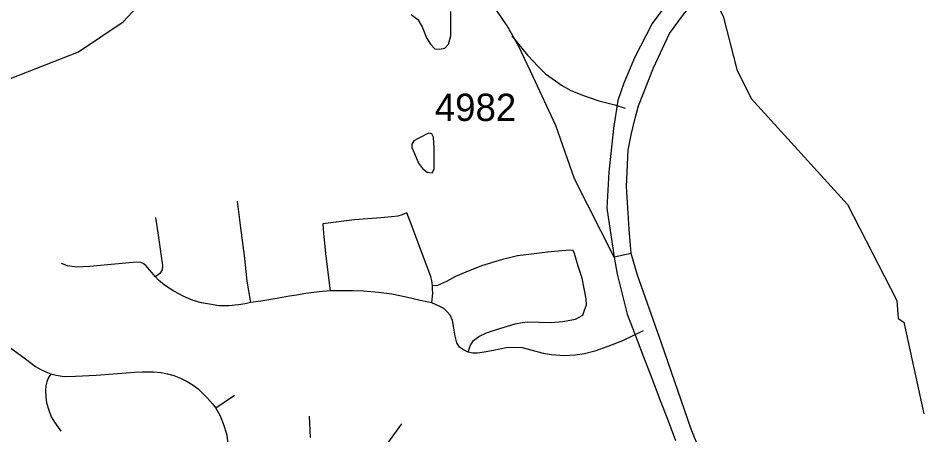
# Model space of a CAD drawing. Extents: x 1383679 to 1536984, y 460658 to 651027.
# Drawn here: x 1442977 to 1447116, y 469651 to 471554 of the extents above; entities that cross this region are included whole.
import ezdxf

# ---------------------------------------------------------------- set-up
doc = ezdxf.new("R2010")
doc.units = 0
for name, color, linetype in [('Exist Hydrographic Creek Single Shore', 7, 'Continuous'), ('Exist Hydrographic Misc Water Feature', 7, 'Continuous'), ('Exist Road Non-System Type 51', 7, 'Continuous'), ('Exist Road Primary US Divided Attributed', 7, 'Continuous'), ('Exist Road Secondary Type 51 Attributed', 7, 'Continuous'), ('Exist Road Secondary Type 51 Number Label', 7, 'Continuous')]:
    doc.layers.add(name, color=color, linetype=linetype)

msp = doc.modelspace()

# ---------------------------------------------------------------- linework, layer by layer
at = {"layer": 'Exist Hydrographic Creek Single Shore'}
msp.add_lwpolyline([(1442699, 471184.5), (1443253.1, 471399.8), (1443456.1, 471536.8), (1443770, 471875.2), (1444283.1, 472075), (1444619, 472242.1), (1444791.1, 472547.2), (1445263.1, 472321.1), (1445451, 472153.2), (1445649.1, 472024.5), (1445764.1, 471913.9), (1446012.1, 471807.1), (1446143.1, 471673.2), (1446199.1, 471563.7), (1446261.1, 471319.6), (1446326.1, 471187), (1446767.1, 470702.1), (1446992.1, 470264.3), (1446999.1, 470182.2), (1447024.1, 470165.2), (1447116.1, 469746.5)], dxfattribs=at)
at = {"layer": 'Exist Hydrographic Misc Water Feature'}
for points in [[(1444773.4, 471570.1), (1444803, 471547.4), (1444822.5, 471515), (1444843.5, 471464.5), (1444861, 471434.6), (1444880.6, 471413.7), (1444902.6, 471411.6), (1444926.7, 471416.8), (1444943, 471434.6), (1444953.7, 471472.9), (1444954.9, 471534.4), (1444953.7, 471584.5)], [(1444811.1, 471007.3), (1444784.9, 470993.8), (1444776.6, 470977.6), (1444776.4, 470963.6), (1444787.9, 470935.5), (1444807, 470890.8), (1444824.6, 470866.6), (1444846.3, 470850.6), (1444868.2, 470847.7), (1444878.6, 470863.9), (1444878.3, 470959.9), (1444875.2, 471010), (1444867.5, 471025.8), (1444851.5, 471028.6), (1444811.1, 471007.3)]]:
    msp.add_lwpolyline(points, dxfattribs=at)
at = {"layer": 'Exist Road Non-System Type 51'}
for p, q in [((1444306.9, 469735.9), (1444312.1, 469639.1)), ((1444729.4, 469701.7), (1444664.4, 469613.3))]:
    msp.add_line(p, q, dxfattribs=at)
for points in [[(1445233, 471473.6), (1445305.2, 471385.4), (1445353.9, 471333.4), (1445386.6, 471300.2), (1445431.8, 471266.9), (1445460, 471247.1), (1445500.1, 471225.2), (1445556.6, 471201.5), (1445631, 471175.7), (1445703, 471157.3), (1445750.9, 471143.5)], [(1443977.9, 470717.7), (1443993.1, 470595.6), (1444009.1, 470469.8), (1444022.1, 470352.2), (1444038.1, 470254.8)], [(1444870.9, 470331.1), (1444868, 470355.8), (1444862.2, 470373.9), (1444820.9, 470485.8), (1444778.6, 470597), (1444753.2, 470665.3), (1444731.4, 470655.2), (1444712.5, 470650.1), (1444683.4, 470645.8), (1444634.8, 470641.3), (1444513.4, 470632.7), (1444369.5, 470615.2), (1444371.6, 470571.6), (1444381.9, 470479.3), (1444393.5, 470379.8), (1444402.9, 470308.5)], [(1443604.6, 470643.8), (1443615.5, 470572.8), (1443627.5, 470487.6), (1443636.2, 470424.3), (1443635.1, 470403.6), (1443624.2, 470388.2), (1443605, 470372.5)], [(1445033, 470028), (1445043.1, 470057.1), (1445057.8, 470081.8), (1445081.6, 470099.2), (1445117.4, 470116.7), (1445163.1, 470131.2), (1445248.9, 470158.1), (1445280.1, 470163.9), (1445306.2, 470166.1), (1445412.4, 470163.9), (1445466.1, 470169), (1445524.2, 470178.4), (1445556.9, 470197.3), (1445565.5, 470220.7), (1445573.6, 470245.1), (1445572, 470271.2), (1445563.9, 470318.7), (1445554, 470366), (1445536, 470421.5), (1445519.8, 470478.7), (1445513.4, 470493.1), (1445498.1, 470493.8), (1445461, 470491.7), (1445395.6, 470485.1), (1445322.2, 470476.4), (1445259, 470468.4), (1445190.6, 470451), (1445094.8, 470421.9), (1445022.9, 470394.2), (1444974.9, 470373.9), (1444934.1, 470351.4), (1444893.5, 470333.2), (1444870.9, 470331.1)], [(1445778.2, 470478.9), (1445700.8, 470462.5)], [(1443605, 470372.5), (1443576.6, 470404.4), (1443560.6, 470424.1), (1443547.6, 470433.5), (1443536.8, 470437.2), (1443519.2, 470438.6), (1443484.4, 470436.4), (1443304.1, 470419), (1443245.4, 470416.1), (1443203.1, 470421.9), (1443175.6, 470432.8)], [(1444038.1, 470254.8), (1444014.1, 470249.7), (1443983.6, 470244.6), (1443939.4, 470239.5), (1443893.5, 470240.2), (1443852.1, 470246.8), (1443814.4, 470254), (1443777.2, 470264.9), (1443733.4, 470283), (1443688.6, 470306.3), (1443645, 470334.7), (1443618.9, 470357.2), (1443605, 470372.5)], [(1444867.4, 470253.3), (1444869.5, 470269.2), (1444871.6, 470297.7), (1444870.9, 470315.8), (1444870.9, 470331.1)], [(1444402.9, 470308.5), (1444352.1, 470304.2), (1444291, 470296.2), (1444248.9, 470288.9), (1444216.9, 470284.6), (1444149.4, 470271.5), (1444086.1, 470261.2), (1444038.1, 470254.8)], [(1444867.4, 470253.3), (1444813.5, 470264.2), (1444749.6, 470280.2), (1444684.9, 470292.5), (1444623.9, 470301.2), (1444554.9, 470306.3), (1444508.4, 470308.5), (1444462.5, 470308.5), (1444402.9, 470308.5)], [(1445033, 470028), (1445012.6, 470038.2), (1444994.5, 470051.2), (1444981.4, 470070.2), (1444973.4, 470100.7), (1444968.4, 470138.5), (1444961.8, 470172.7), (1444950.9, 470196.6), (1444939.2, 470211.2), (1444921.9, 470227.2), (1444901.5, 470238.8), (1444867.4, 470253.3)], [(1442852.9, 470119.2), (1442898.5, 470081.7), (1442954.6, 470038.8), (1443010.8, 469997.1), (1443056.4, 469963.4), (1443080.1, 469949.6), (1443103.9, 469937.7), (1443126.9, 469929.1)], [(1445833.1, 470125.2), (1445738.6, 470080.3), (1445671.1, 470054.2), (1445612.9, 470032.4), (1445565.6, 470020.8), (1445522.1, 470014.2), (1445472.6, 470012), (1445414.5, 470016.4), (1445378.1, 470022.2), (1445321.5, 470037.5), (1445281.5, 470048.3), (1445244.5, 470049.8), (1445207.4, 470047.7), (1445148.6, 470036), (1445107.1, 470028.8), (1445075.9, 470024.4), (1445054.9, 470024.4), (1445033, 470028)], [(1443126.9, 469929.1), (1443114.4, 469909.3), (1443108.5, 469893.4), (1443103.9, 469874.3), (1443101.9, 469853.8), (1443103.4, 469824.1), (1443105.9, 469797.1), (1443116.4, 469762.8), (1443128.2, 469733), (1443142.9, 469707.9), (1443172.5, 469667.7)], [(1443126.9, 469929.1), (1443150.1, 469923.2), (1443187.6, 469917.2), (1443239.1, 469918.6), (1443333.6, 469923.8), (1443410.9, 469929.8), (1443470.9, 469934.4), (1443508.6, 469937), (1443545.6, 469938.3), (1443595.8, 469939), (1443630.8, 469935.8), (1443659.1, 469929.8), (1443689, 469921.3), (1443719.2, 469910), (1443749.6, 469894.1), (1443776, 469878.2), (1443799.1, 469860.4), (1443820.2, 469839.3), (1443842, 469818.8), (1443865.1, 469792.4), (1443881, 469773.2)], [(1443964.9, 469830.1), (1443927.9, 469805), (1443881, 469773.2)], [(1443881, 469773.2), (1443898.1, 469740.9), (1443913.4, 469702.7), (1443930.6, 469650), (1443938.2, 469576.2), (1443942, 469450), (1443940.4, 469340.2), (1443941.1, 469267.5)]]:
    msp.add_lwpolyline(points, dxfattribs=at)
at = {"layer": 'Exist Road Primary US Divided Attributed'}
for points in [[(1446944.2, 472703.3), (1446672, 472394.9), (1446335, 472038.6), (1446002, 471702.8), (1445874.1, 471529.1), (1445793.1, 471372), (1445744.4, 471256.4), (1445717.2, 471177.1), (1445697.2, 471049.5), (1445675.9, 470851), (1445667.4, 470685.7), (1445700.8, 470462.5)], [(1445778.2, 470478.9), (1445769.7, 470590.6), (1445756.9, 470784.9), (1445765.4, 470950.3), (1445778.2, 471020.6), (1445793.1, 471085), (1445812.3, 471152.9), (1445880.5, 471326.5), (1445953, 471483.6), (1446016.9, 471570.5), (1446132, 471711), (1446340.8, 471938.4), (1446639.2, 472265.1), (1447000.3, 472660.9)], [(1446510.4, 468077.2), (1446514.9, 468128.1), (1446498.5, 468391), (1446434.6, 468688.7), (1446311, 469036), (1446053.1, 469676.8), (1445916.7, 470069.6), (1445808, 470379.7), (1445778.2, 470478.9)], [(1445700.8, 470462.5), (1445714.3, 470383.8), (1445760.6, 470201.4), (1445793.4, 470114.3), (1445834.5, 470006.3), (1445877.4, 469896.6), (1445911.4, 469806.9), (1445942.4, 469726.4), (1445981.1, 469624.7)]]:
    msp.add_lwpolyline(points, dxfattribs=at)
at = {"layer": 'Exist Road Secondary Type 51 Attributed'}
for points in [[(1445700.8, 470462.5), (1445519.9, 470819.5), (1445434.7, 471063.4), (1445329, 471289.6), (1445264.4, 471424.8), (1445211.5, 471518.8), (1445143.4, 471618.8)], [(1445778.2, 470478.9), (1445700.8, 470462.5)]]:
    msp.add_lwpolyline(points, dxfattribs=at)

# ---------------------------------------------------------------- texts
at = {"layer": 'Exist Road Secondary Type 51 Number Label'}
msp.add_text('4982', height=125, dxfattribs=at).set_placement((1444881.1, 471084.1))

doc.saveas('drawing.dxf')
